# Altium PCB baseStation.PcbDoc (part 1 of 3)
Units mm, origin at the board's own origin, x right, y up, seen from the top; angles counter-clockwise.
Board outline 130 x 90 mm, 4 copper layers (Top Layer, Ground Layer, Power Layer, Bottom Layer), stack 1.574 mm thick; 252 components, 154 nets, 772 pads, 1223 vias.
Unrouted connection lines stored in the file: 134.
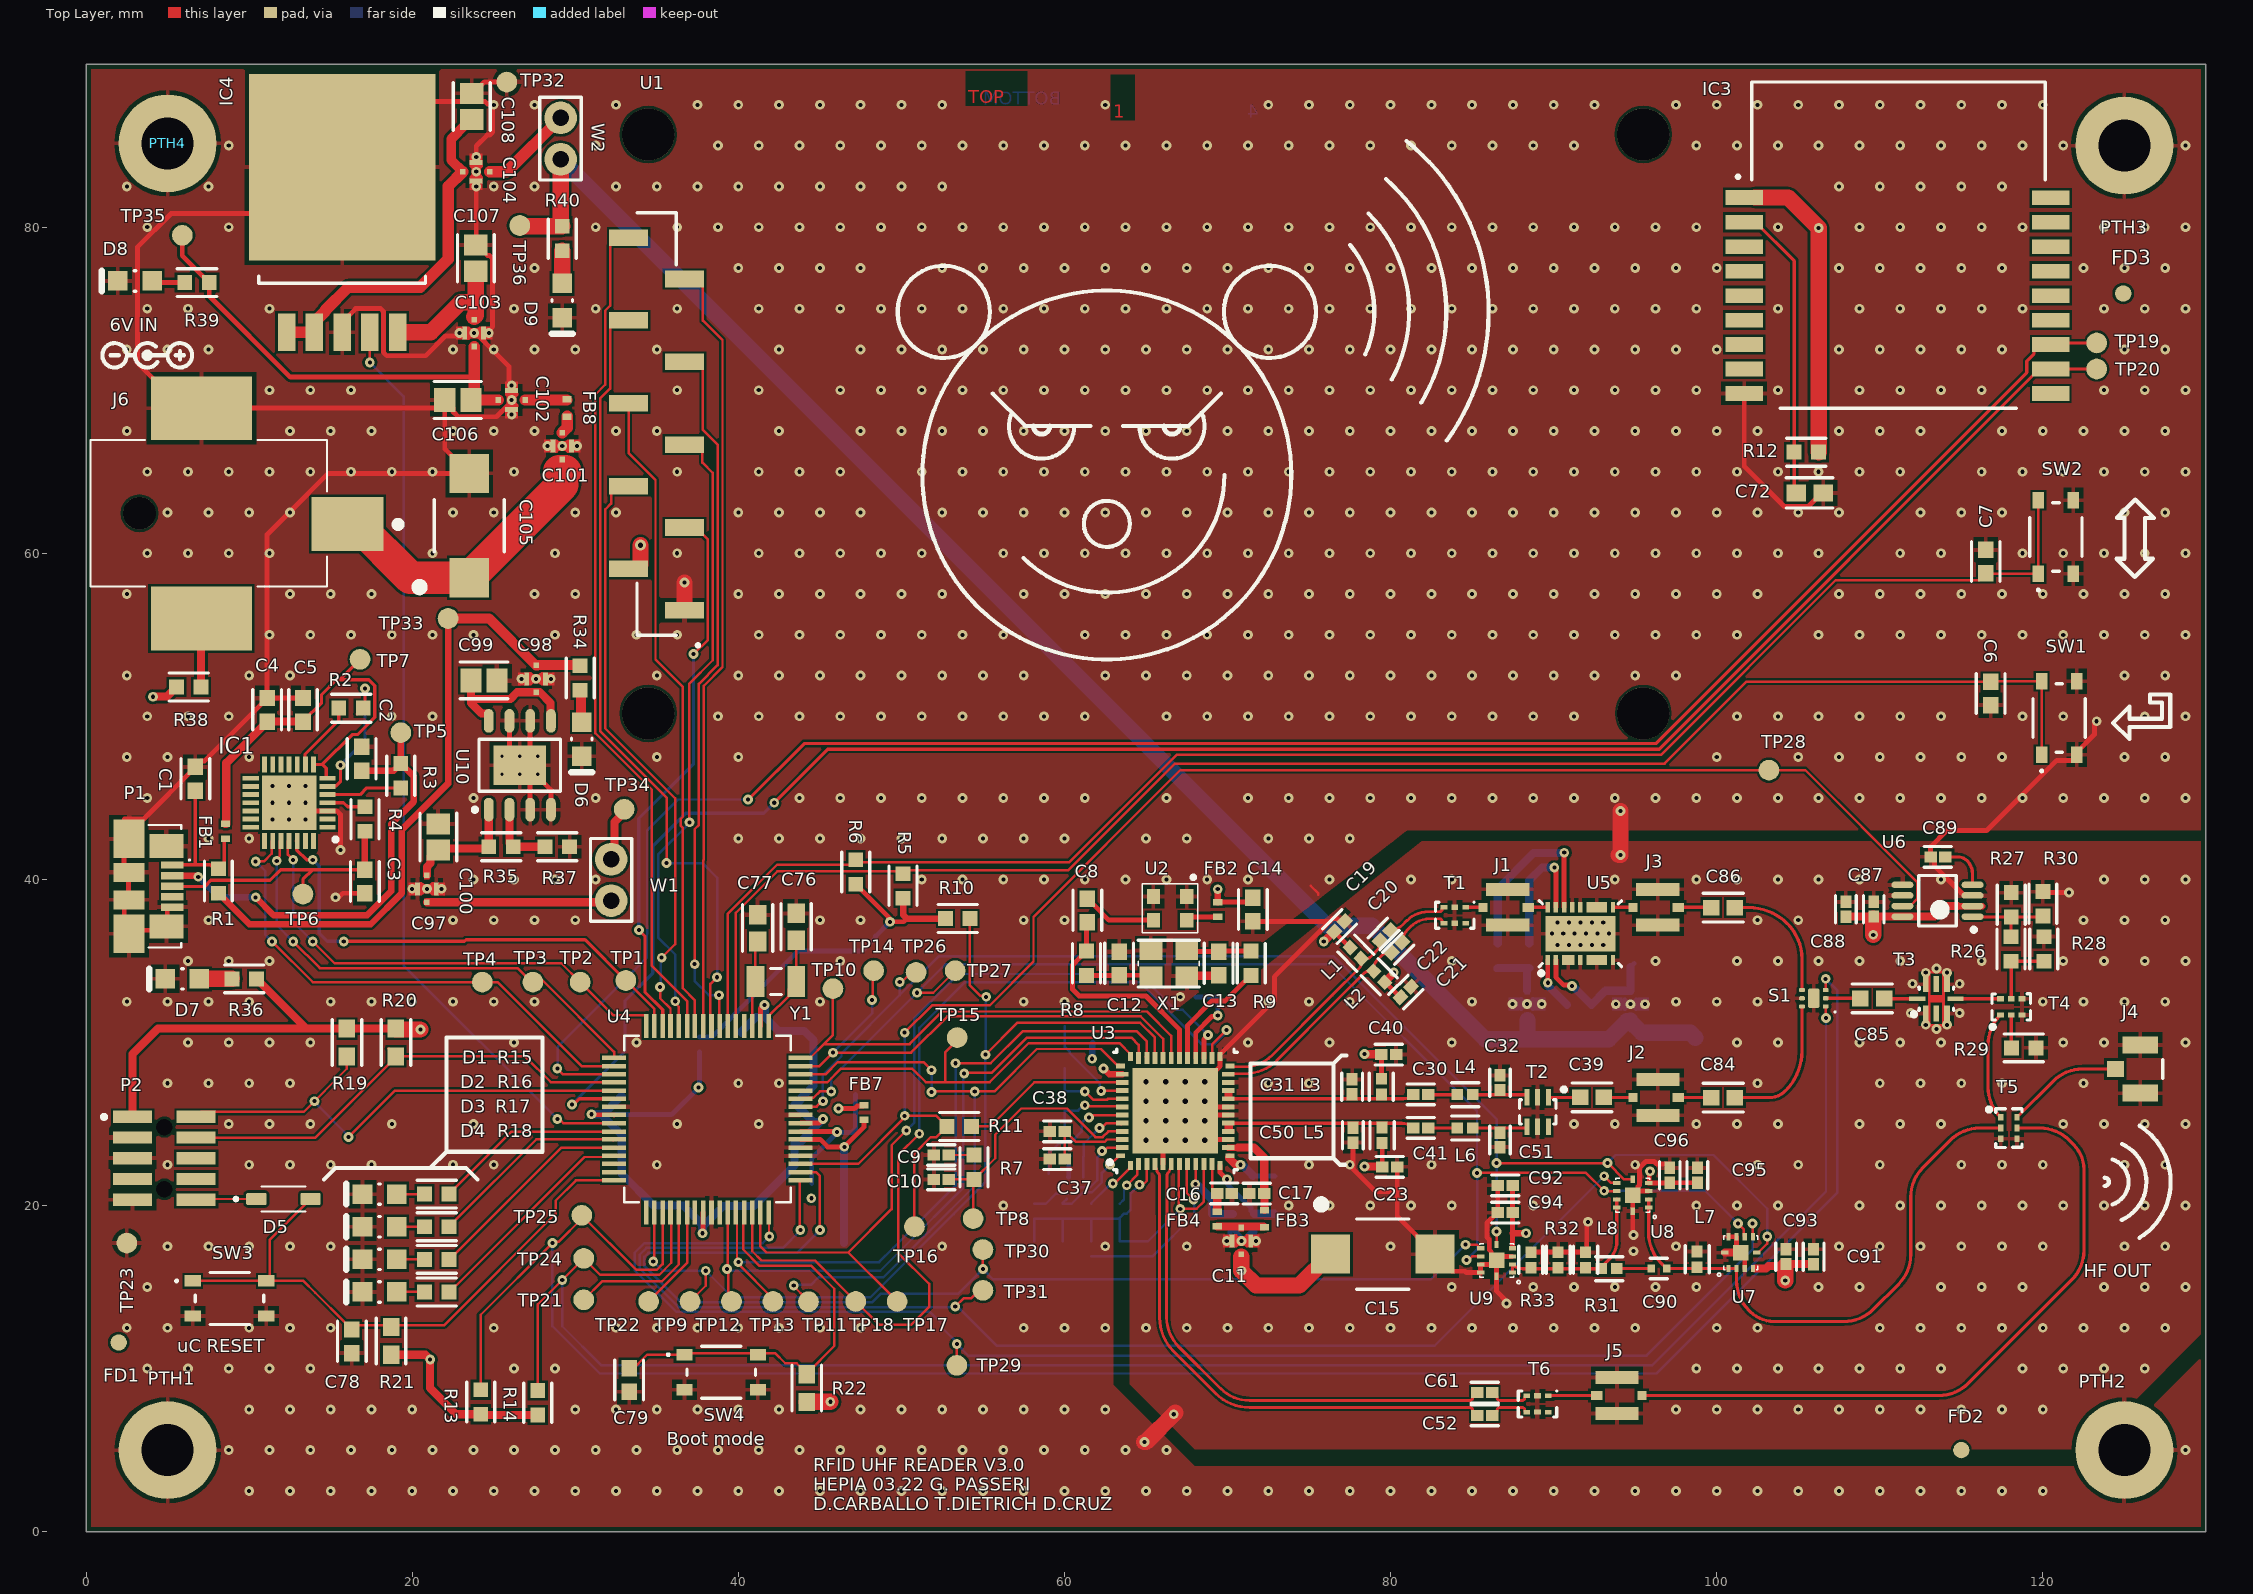
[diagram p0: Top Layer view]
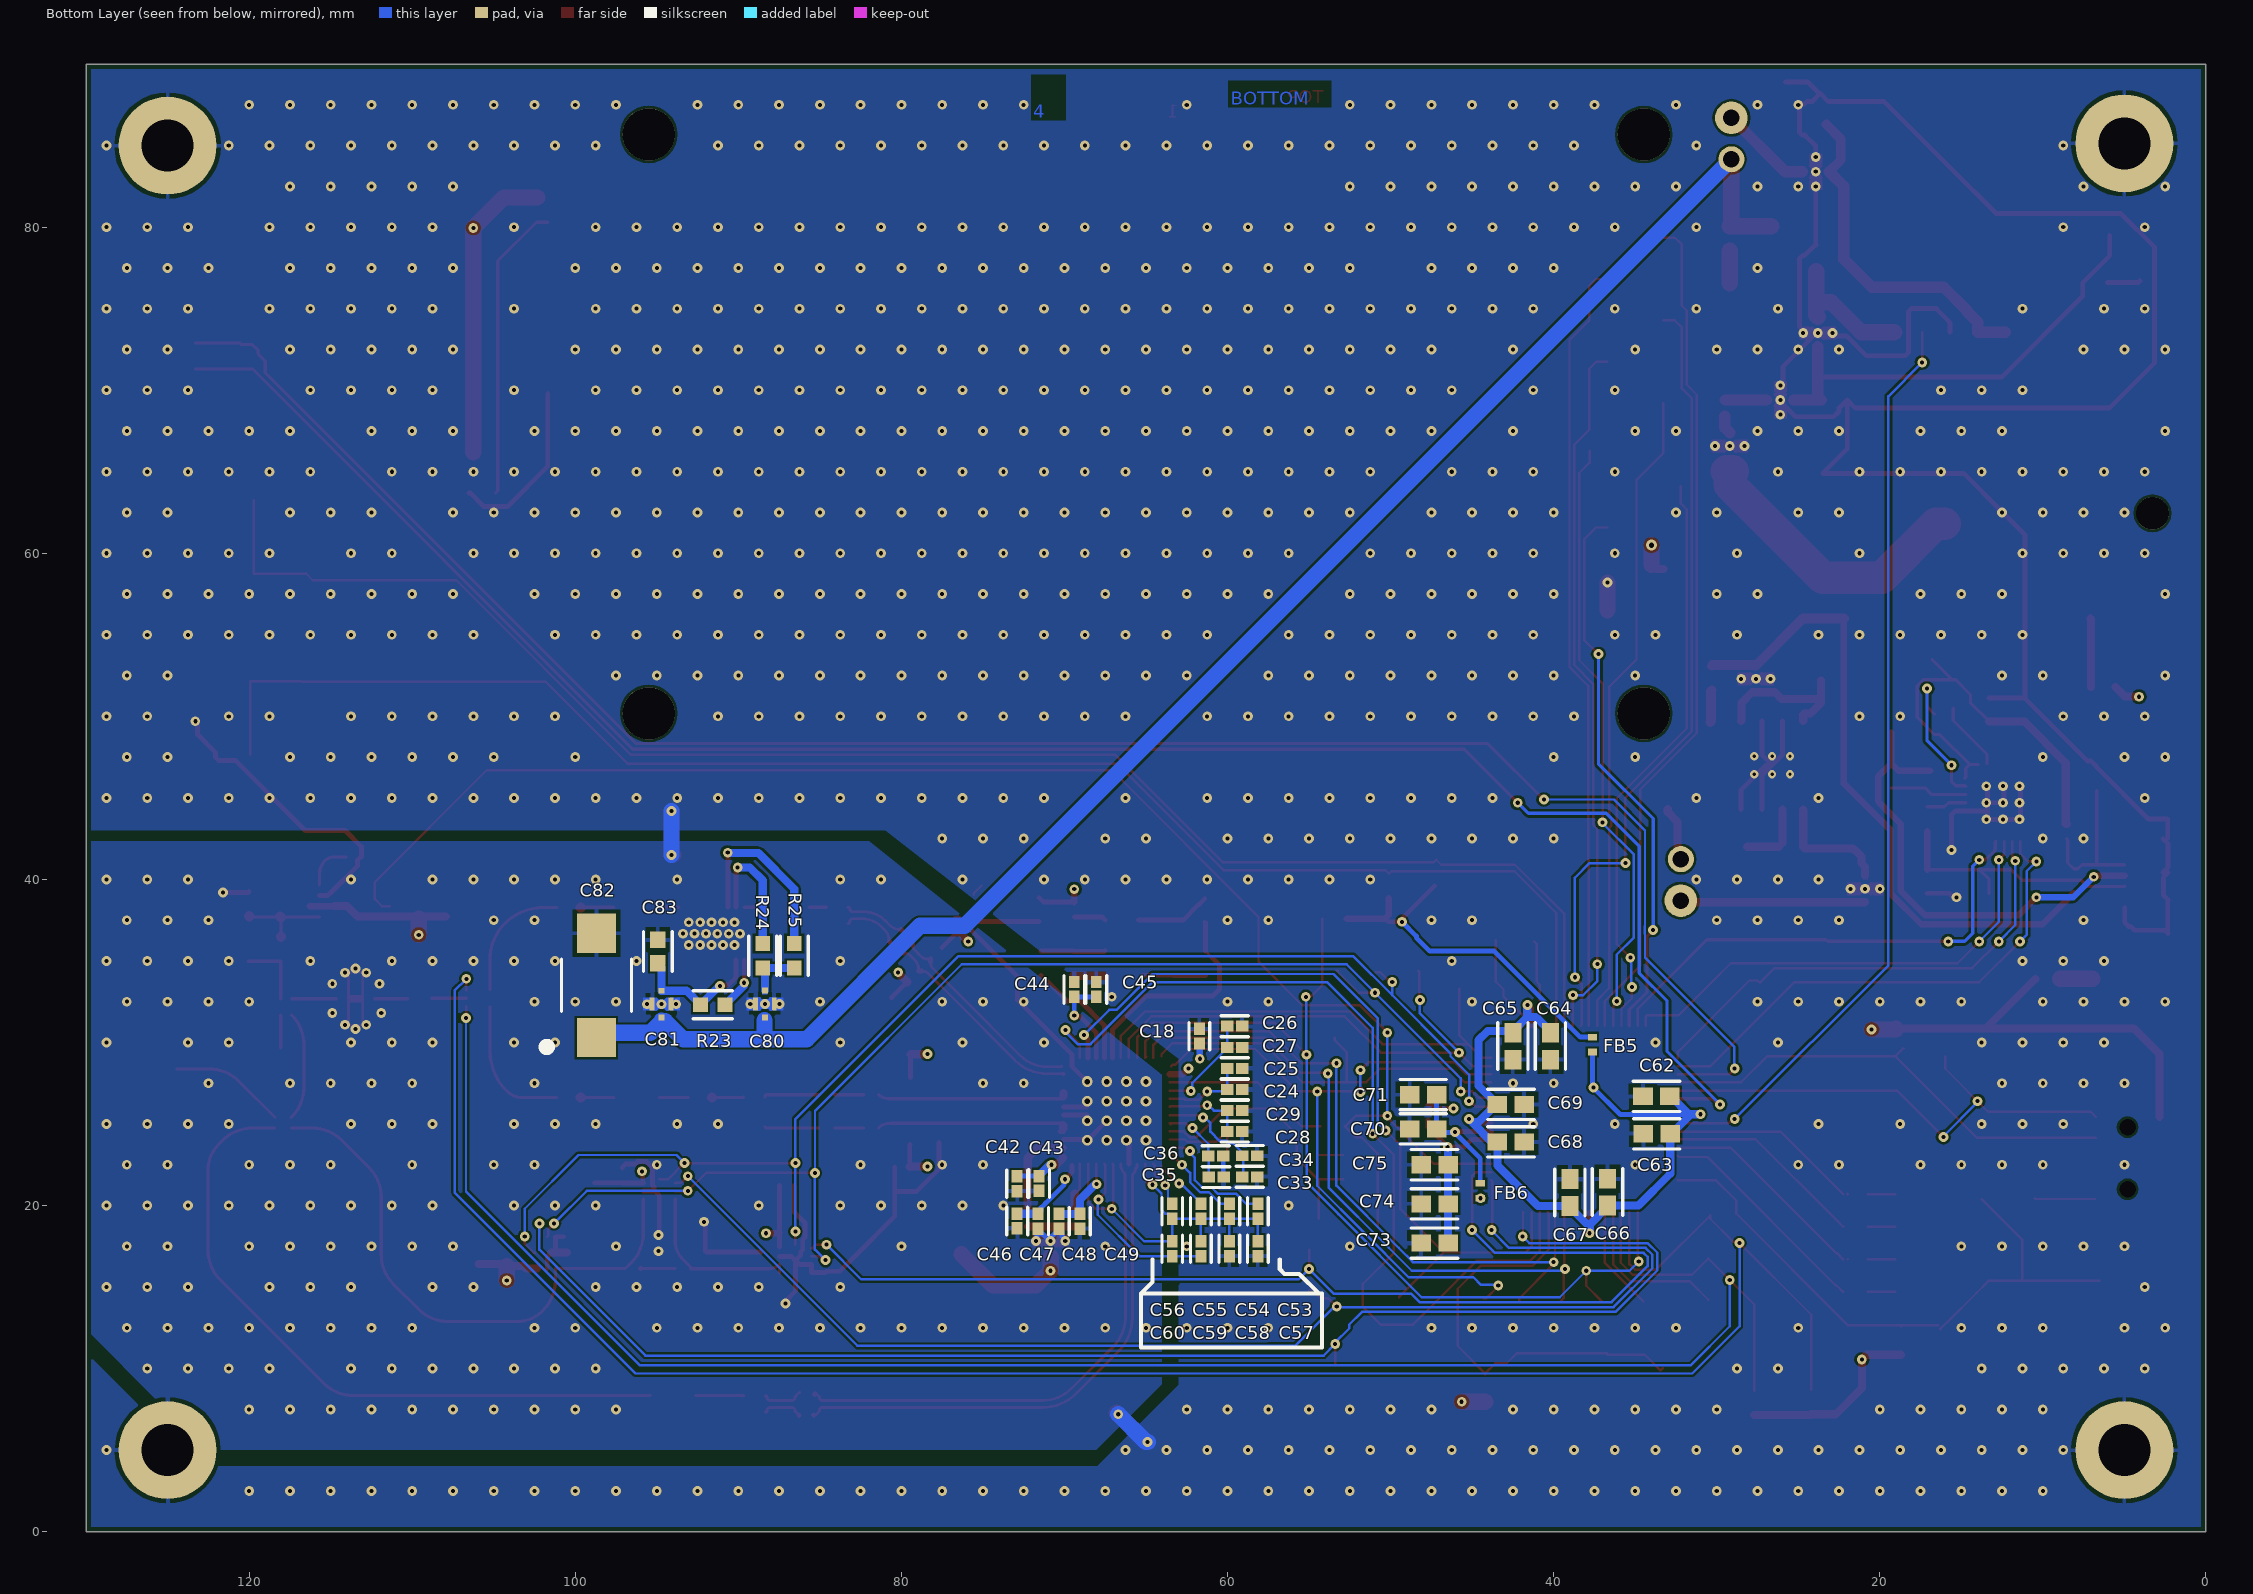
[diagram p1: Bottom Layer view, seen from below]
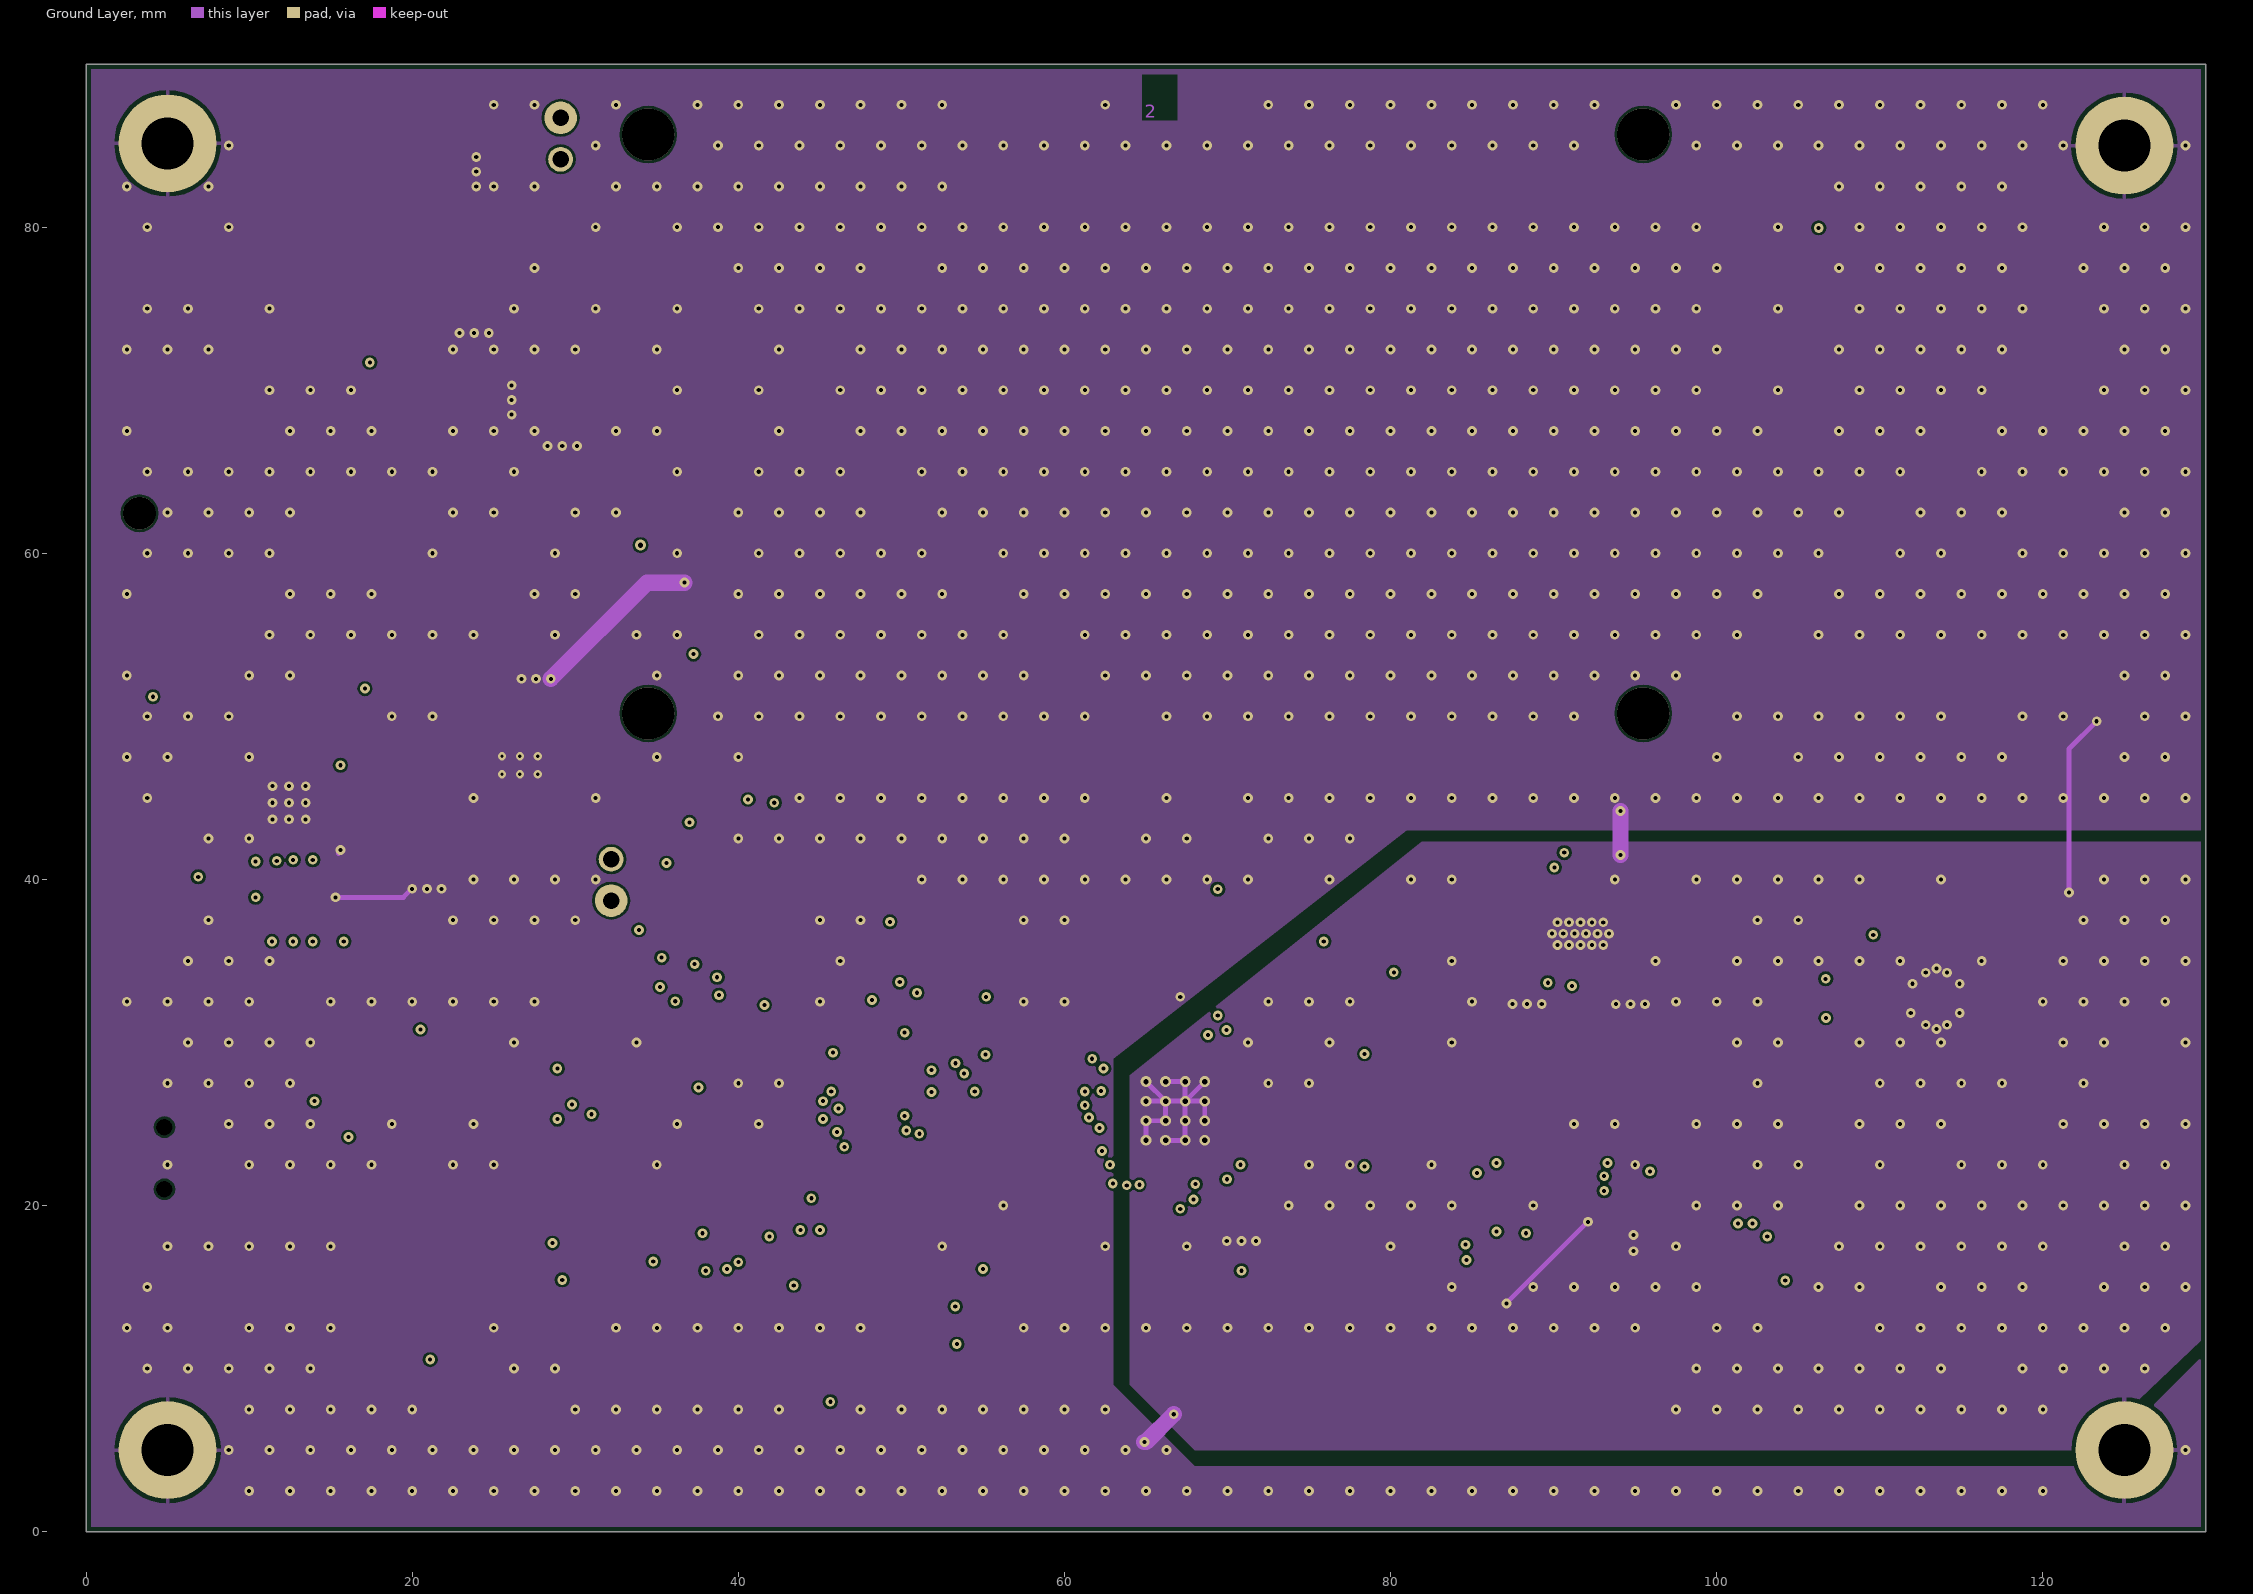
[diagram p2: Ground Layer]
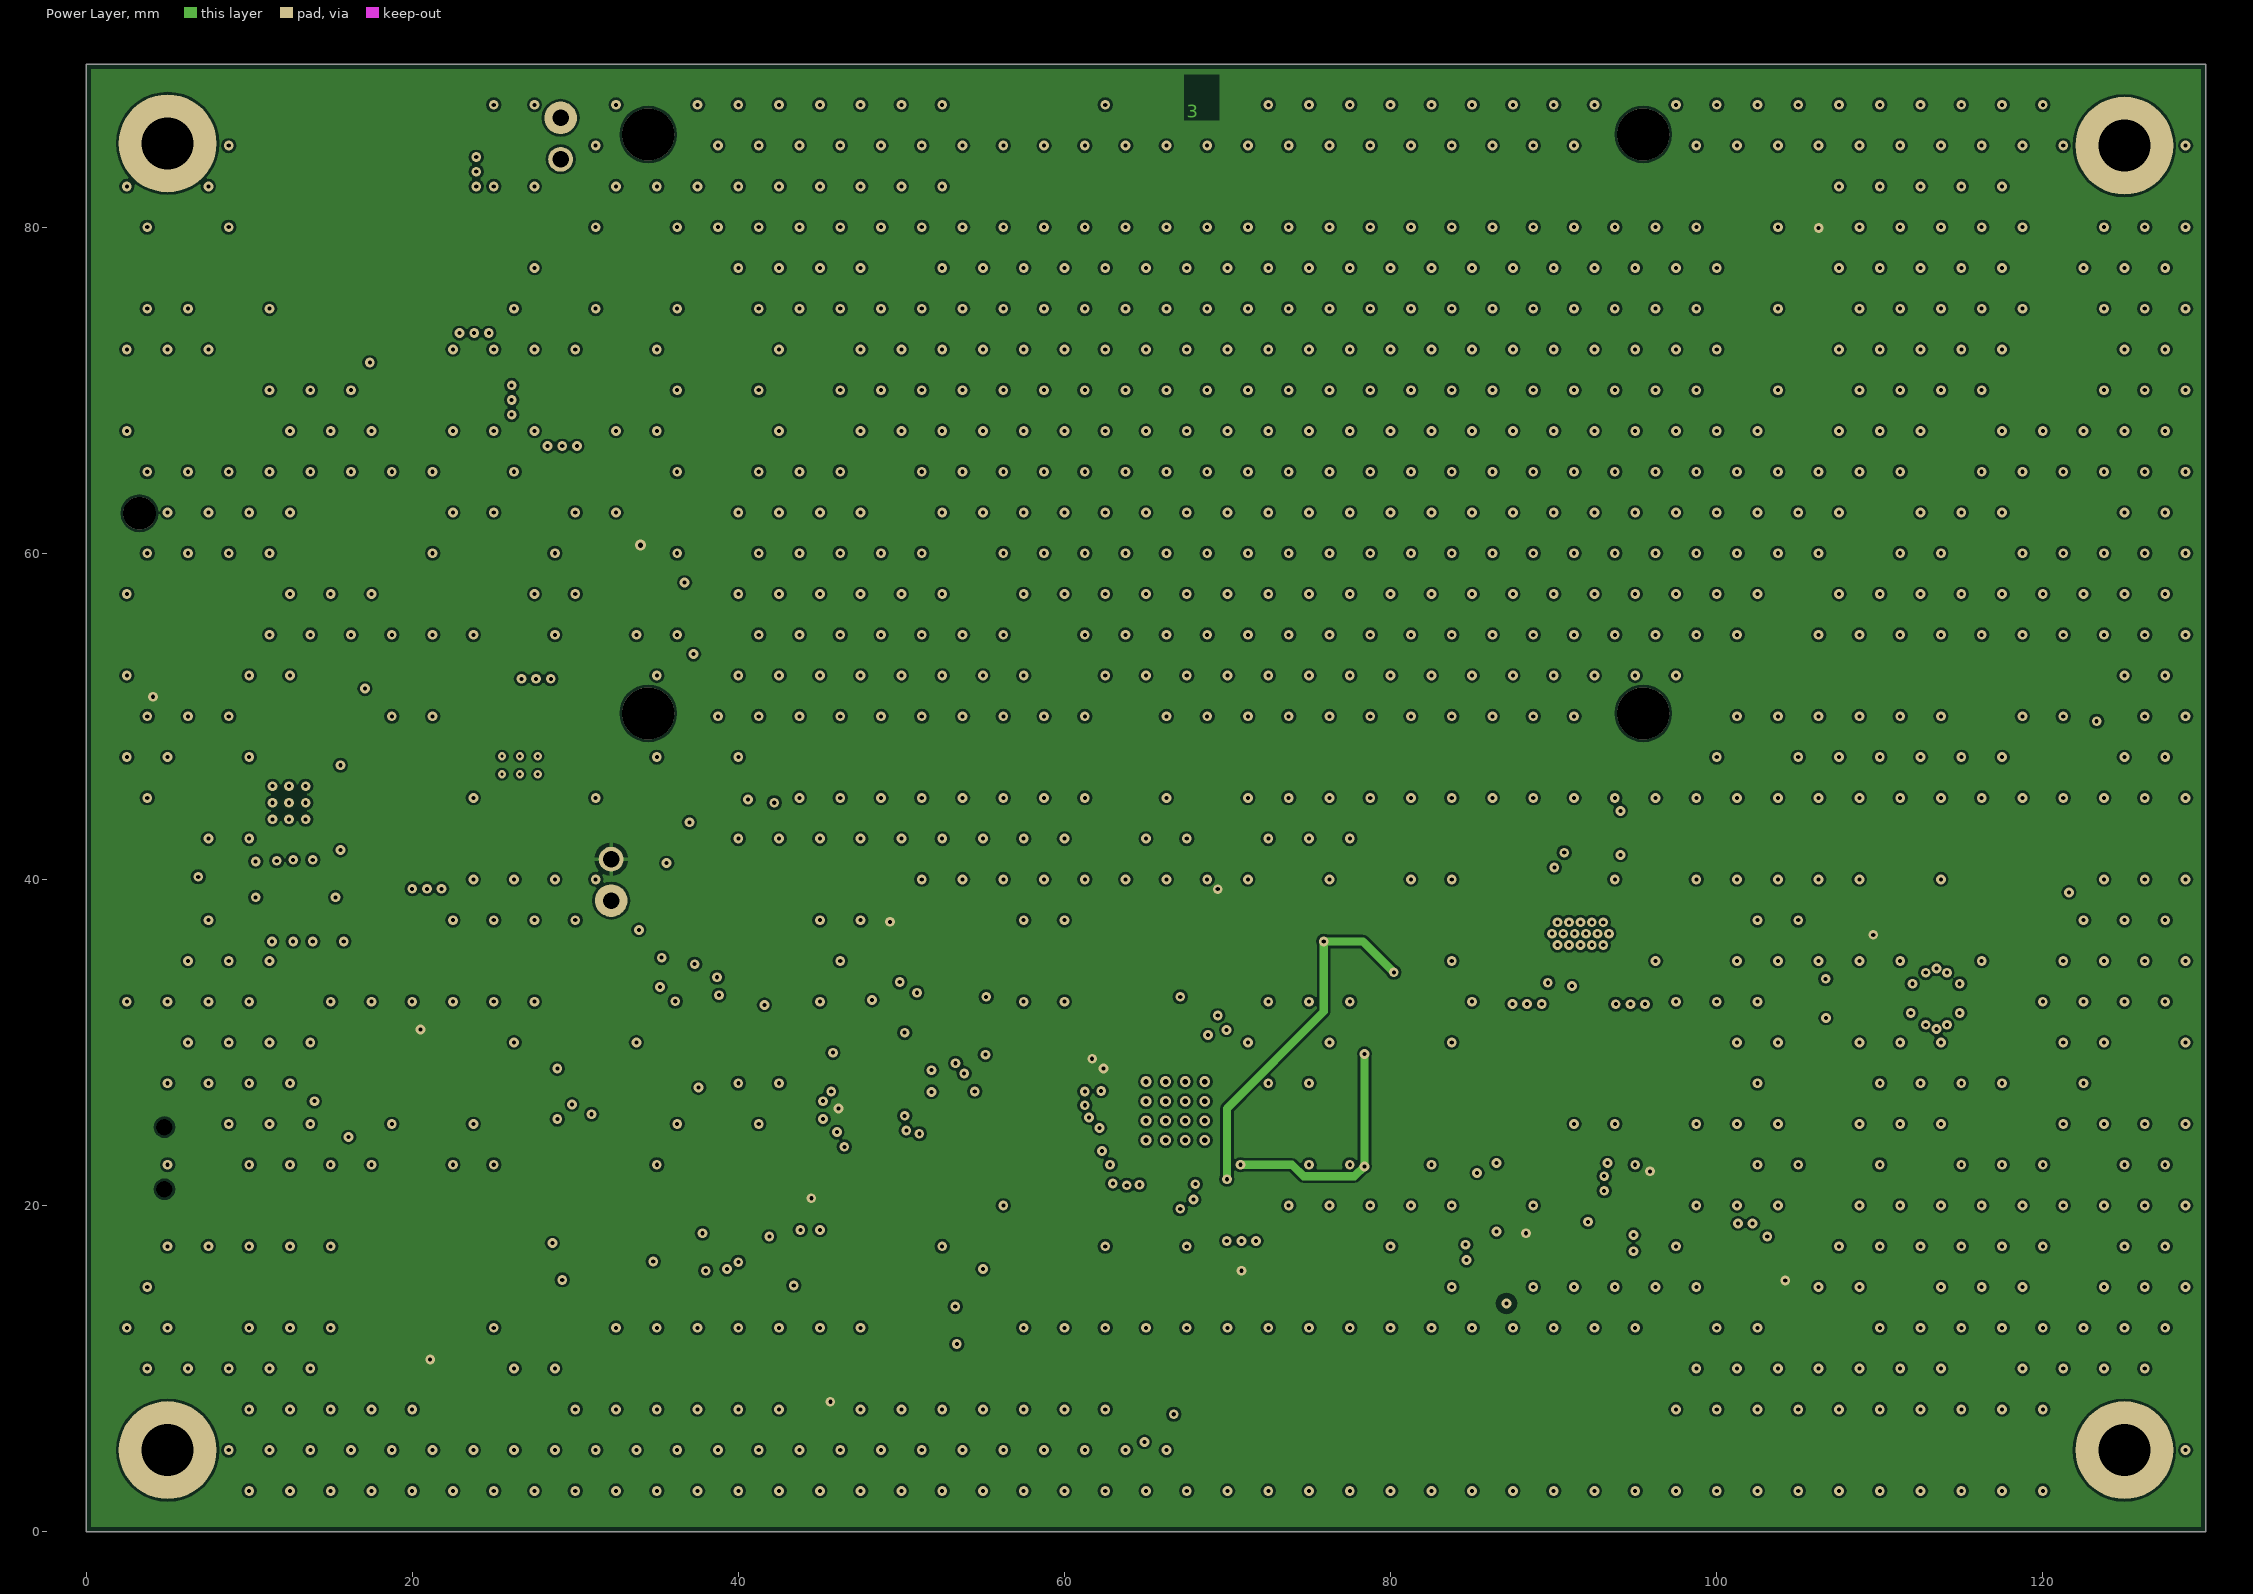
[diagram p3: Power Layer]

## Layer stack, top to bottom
Top Solder: solder mask 0.0102, Solder Resist, Dk 3.5
Top Layer: signal copper 0.035
Dielectric 1: prepreg 0.1168, PP-016, Dk 4.4
Ground Layer: signal copper 0.035
Dielectric 2: core 1.2, FR-4, Dk 4.3
Power Layer: signal copper 0.035
Dielectric 3: prepreg 0.1168, PP-016, Dk 4.4
Bottom Layer: signal copper 0.035
Bottom Solder: solder mask 0.0102, Solder Resist, Dk 3.5

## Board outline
0,0 130,0 130,90 0,90

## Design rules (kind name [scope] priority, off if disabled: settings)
BoardOutlineClearance [All] p1: gap=0.3 ignorepadtopadclearanceinfootprint=FALSE
Clearance [All] p1: gap=0.15 ignorepadtopadclearanceinfootprint=FALSE
DiffPairsRouting [All] p1: maxlimit=0.254 minlimit=0.254 mostfreqgap=0.254 toplayer_minwidth=0.381 toplayer_maxwidth=0.381 toplayer_prefwidth=0.381 midlayer1_minwidth=0.381 midlayer1_maxwidth=0.381 midlayer1_prefwidth=0.381 midlayer2_minwidth=0.381 midlayer2_maxwidth=0.381 midlayer2_prefwidth=0.381 bottomlayer_minwidth=0.381 bottomlayer_maxwidth=0.381 bottomlayer_prefwidth=0.381 maxuncoupledlength=12.7
HoleSize [All] p1: absolutevalues=TRUE maxlimit=3.3 minlimit=0.025 maxpercent=80.000 minpercent=20.000
MaxMinImpedance "Schematic Impedance Constraint_35" [InNet('IN_P')] p1: minimum=100,0 maximum=100,0
MaxMinImpedance "Schematic Impedance Constraint_34" [InNet('TX_P')] p2: minimum=100,0 maximum=100,0
MaxMinImpedance "Schematic Impedance Constraint_33" [InNet('IN_N')] p3: minimum=100,0 maximum=100,0
MaxMinImpedance "Schematic Impedance Constraint_32" [InNet('TX_N')] p4: minimum=100,0 maximum=100,0
MaxMinImpedance "Schematic Impedance Constraint_31" [InNet('RFO_P')] p5: minimum=100,0 maximum=100,0
MaxMinImpedance "Schematic Impedance Constraint_30" [InNet('RFO_N')] p6: minimum=100,0 maximum=100,0
MaxMinImpedance "Schematic Impedance Constraint_29" [InNet('RX_N')] p7: minimum=100,0 maximum=100,0
MaxMinImpedance "Schematic Impedance Constraint_28" [InNet('RX_P')] p8: minimum=100,0 maximum=100,0
MaxMinImpedance "Schematic Impedance Constraint_27" [InNet('NetT3_4')] p9: minimum=50,00 maximum=50,00
MaxMinImpedance "Schematic Impedance Constraint_26" [InNet('NetC84_2')] p10: minimum=50,00 maximum=50,00
MaxMinImpedance "Schematic Impedance Constraint_25" [InNet('NetR29_1')] p11: minimum=50,00 maximum=50,00
MaxMinImpedance "Schematic Impedance Constraint_24" [InNet('TX')] p12: minimum=50,00 maximum=50,00
MaxMinImpedance "Schematic Impedance Constraint_23" [InNet('NetC30_2')] p13: minimum=50,00 maximum=50,00
MaxMinImpedance "Schematic Impedance Constraint_22" [InNet('NetC86_1')] p14: minimum=50,00 maximum=50,00
MaxMinImpedance "Schematic Impedance Constraint_21" [InNet('NetR26_2')] p15: minimum=50,00 maximum=50,00
MaxMinImpedance "Schematic Impedance Constraint_20" [InNet('NetC39_2')] p16: minimum=50,00 maximum=50,00
MaxMinImpedance "Schematic Impedance Constraint_19" [InNet('NetL8_1')] p17: minimum=50,00 maximum=50,00
MaxMinImpedance "Schematic Impedance Constraint_18" [InNet('CCC')] p18: minimum=50,00 maximum=50,00
MaxMinImpedance "Schematic Impedance Constraint_17" [InNet('NetC39_1')] p19: minimum=50,00 maximum=50,00
MaxMinImpedance "Schematic Impedance Constraint_16" [InNet('PA_OUT')] p20: minimum=50,00 maximum=50,00
MaxMinImpedance "Schematic Impedance Constraint_15" [InNet('NetJ5_OUT')] p21: minimum=50,00 maximum=50,00
MaxMinImpedance "Schematic Impedance Constraint_14" [InNet('NetC86_2')] p22: minimum=50,00 maximum=50,00
MaxMinImpedance "Schematic Impedance Constraint_13" [InNet('NetJ5_IN')] p23: minimum=50,00 maximum=50,00
MaxMinImpedance "Schematic Impedance Constraint_12" [InNet('NetC85_1')] p24: minimum=50,00 maximum=50,00
MaxMinImpedance "Schematic Impedance Constraint_11" [InNet('NetC84_1')] p25: minimum=50,00 maximum=50,00
MaxMinImpedance "Schematic Impedance Constraint_10" [InNet('NetC51_2')] p26: minimum=50,00 maximum=50,00
MaxMinImpedance "Schematic Impedance Constraint_9" [InNet('PAOUT_N')] p27: minimum=50,00 maximum=50,00
MaxMinImpedance "Schematic Impedance Constraint_8" [InNet('NetC41_2')] p28: minimum=50,00 maximum=50,00
MaxMinImpedance "Schematic Impedance Constraint_7" [InNet('TX_RX')] p29: minimum=50,00 maximum=50,00
MaxMinImpedance "Schematic Impedance Constraint_6" [InNet('NetC32_2')] p30: minimum=50,00 maximum=50,00
MaxMinImpedance "Schematic Impedance Constraint_5" [InNet('LP_FILTER_IN')] p31: minimum=50,00 maximum=50,00
MaxMinImpedance "Schematic Impedance Constraint_4" [InNet('NetC90_1')] p32: minimum=50,00 maximum=50,00
MaxMinImpedance "Schematic Impedance Constraint_3" [InNet('NetJ1_OUT')] p33: minimum=50,00 maximum=50,00
MaxMinImpedance "Schematic Impedance Constraint_2" [InNet('NetR26_1')] p34: minimum=50,00 maximum=50,00
MaxMinImpedance "Schematic Impedance Constraint_1" [InNet('PAOUT_P')] p35: minimum=50,00 maximum=50,00
MaxMinImpedance "Schematic Impedance Constraint" [InNet('NetJ1_IN')] p36: minimum=50,00 maximum=50,00
MinimumSolderMaskSliver [All] p1: minsoldermaskwidth=0.075
PlaneConnect [All] p1: pad.planeconnectstyle=Relief pad.reliefexpansion=0.508 pad.reliefentries=4 pad.reliefconductorwidth=0.254 pad.reliefairgap=0.254 via.planeconnectstyle=Direct via.reliefexpansion=0.508 via.reliefentries=4 via.reliefconductorwidth=0.254 via.reliefairgap=0.254
PolygonConnect [All] p1: thpad.connectstyle=Relief thpad.reliefconductorwidth=0.254 thpad.reliefentries=4 thpad.polygonreliefangle="90 Angle" thpad.airgapwidth=0.254 smdpad.connectstyle=Relief smdpad.reliefconductorwidth=0.254 smdpad.reliefentries=4 smdpad.polygonreliefangle="90 Angle" smdpad.airgapwidth=0.254 via.connectstyle=Direct via.reliefconductorwidth=0.254 via.reliefentries=4 via.polygonreliefangle="90 Angle" via.airgapwidth=0.254
RoutingVias [All] p1: holewidth=0.711 width=1 viastyle="Through Hole" minholewidth=0.5 minwidth=0.7 maxholewidth=0.711 maxwidth=1
SilkToSolderMaskClearance [IsPad] p1: minsilkscreentomaskgap=0 clearancetoexposedcopper=TRUE
SolderMaskExpansion [All] p1: expansion=0.03 istentingtop=FALSE
Width [All] p1: maxlimit=2 minlimit=0.15 preferedwidth=0.15
25 further rules are at their usual default settings.

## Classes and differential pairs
component class Sheet6: C87 C88 C89 C90 C91 C92 C93 C94 C95 C96 J4 J5 L7 L8 R26 R27 R28 R29 R30 R31 R32 R33 T4 T5 T6 TP26 TP27 TP28 TP29 TP30 TP31 U6 U7 U8 U9
component class Sheet5: C80 C81 C82 C83 C84 C85 C86 J3 R23 R24 R25 S1 T3 TP24 TP25 U5
component class Sheet4: C8 C9 C10 C11 C12 C13 C14 C15 C16 C17 C18 C19 C20 C21 C22 C23 C24 C25 C26 C27 C28 C29 C30 C31 C32 C33 C34 C35 C36 C37 C38 C39 C40 C41 C42 C43 C44 C45 C46 C47 C48 C49 C50 C51 C52 C53 C54 C55 C56 C57 C58 C59 C60 C61 FB2 FB3 FB4 J1 J2 L1 L2 L3 L4 L5 L6 R7 R8 R9 R10 R11 T1 T2 TP8 TP9 TP10 TP11 TP12 TP13 TP14 TP15 TP16 TP17 TP18 U2 U3 X1
component class Sheet3: C62 C63 C64 C65 C66 C67 C68 C69 C70 C71 C72 C73 C74 C75 C76 C77 C78 C79 D1 D2 D3 D4 D5 FB5 FB6 FB7 IC3 P2 R12 R13 R14 R15 R16 R17 R18 R19 R20 R21 R22 SW3 SW4 TP19 TP20 TP21 TP22 TP23 U4 Y1
component class Sheet2: C1 C2 C3 C4 C5 C6 C7 FB1 IC1 P1 R1 R2 R3 R4 R5 R6 SW1 SW2 TP1 TP2 TP3 TP4 TP5 TP6 TP7 U1
component class Sheet1: C97 C98 C99 C100 C101 C102 C103 C104 C105 C106 C107 C108 D6 D7 D8 D9 FB8 IC4 J6 R34 R35 R36 R37 R38 R39 R40 TP32 TP33 TP34 TP35 TP36 U10 W1 W2
component class baseStation: FD1 FD2 FD3 PTH1 PTH2 PTH3 PTH4
differential pair TX: +TX_P -TX_N
differential pair RFO: +RFO_P -RFO_N
differential pair RX: +RX_P -RX_N
differential pair IN: +IN_P -IN_N

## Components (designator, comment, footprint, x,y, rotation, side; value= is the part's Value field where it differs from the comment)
C1 "Cap" FP-C0603C-CF-IPC_B 6.7,46.174 r270 top value=10nF
C2 "Cap" FP-C0603C-CF-IPC_B 16.9,47.4 r270 top value=47pF
C3 "Cap" FP-C0603C-CF-IPC_B 17.1,39.874 r90 top value=47pF
C4 "Cap" FP-C0603C-CF-IPC_B 11.1,50.4 r270 top value=4u7F
C5 "Cap" FP-C0603C-CF-IPC_B 13.3,50.4 r270 top value=100nF
C6 "Cap" FP-C0603C-CF-IPC_B 116.8,51.4 r90 top value=100nF
C7 "Cap" FP-C0603C-CF-IPC_B 116.5,59.5 r270 top value=100nF
C8 "" FP-C0603C-CF-IPC_B 61.4,38.1 r270 top value=220nF
C9 "" FP-PRF15-0_05-IPC_A 52.45,23.1 r180 top value=3n9F
C10 "" FP-PRF15-0_05-IPC_A 52.45,21.6 r180 top value=150pF
C11 "0.47uF" NFM18PS 70.85,17.83 r90 top
C12 "" FP-C0603C-CF-IPC_B 63.35,34.85 r90 top value=11pF
C13 "" FP-C0603C-CF-IPC_B 69.45,34.85 r270 top value=11pF
C14 "" FP-C0603C-CF-IPC_B 71.55,38.15 r270 top value=100nF
C15 "" 2917(7343) 79.52,17.02 r0 top
C16 "Cap" FP-PRF15-0_05-IPC_A 69.814,20.74 r0 top value=2u2F
C17 "Cap" FP-PRF15-0_05-IPC_A 71.8,20.73 r180 top value=2u2F
C18 "Low ESL" FP-PRF15-0_05-IPC_A 61.73,30.394 r90 bottom value=100nF
C19 "Cap" FP-PRF15-0_05-IPC_A 76.87,37.11 r45 top value=120pF
C20 "Cap" FP-PRF15-0_05-IPC_A 79.662,36.572 r45 top value=82pF
C21 "Cap" FP-PRF15-0_05-IPC_A 80.93,33.09 r45 top value=120pF
C22 "Cap" FP-PRF15-0_05-IPC_A 80.39,35.83 r45 top value=82pF
C23 "Cap" FP-PRF15-0_05-IPC_A 79.95,22.37 r0 top value=120pF
C24 "Cap" FP-PRF15-0_05-IPC_A 59.556,27.117 r180 bottom value=2u2F
C25 "Cap" FP-PRF15-0_05-IPC_A 59.556,28.411 r180 bottom value=120pF
C26 "Cap" FP-PRF15-0_05-IPC_A 59.556,31 r180 bottom value=2u2F
C27 "Cap" FP-PRF15-0_05-IPC_A 59.556,29.706 r180 bottom value=120pF
C28 "Cap" FP-PRF15-0_05-IPC_A 59.556,24.528 r180 bottom value=2u2F
C29 "Cap" FP-PRF15-0_05-IPC_A 59.556,25.822 r180 bottom value=120pF
C30 "Cap" FP-PRF15-0_05-IPC_A 81.85,26.82 r0 top value=15pF
C31 "Cap" FP-PRF15-0_05-IPC_A 77.64,27.29 r90 top value=1p2F
C32 "Cap" FP-PRF15-0_05-IPC_A 86.71,27.54 r270 top value=5p6F
C33 "Cap" FP-PRF15-0_05-IPC_A 58.636,21.759 r180 bottom value=2u2F
C34 "Cap" FP-PRF15-0_05-IPC_A 58.636,23.053 r180 bottom value=30pF
C35 "Cap" FP-PRF15-0_05-IPC_A 60.7,21.74 r180 bottom value=2u2F
C36 "Cap" FP-PRF15-0_05-IPC_A 60.73,23.03 r180 bottom value=30pF
C37 "Cap" FP-PRF15-0_05-IPC_A 59.55,22.85 r180 top value=2u2F
C38 "Cap" FP-PRF15-0_05-IPC_A 59.55,24.55 r180 top value=120pF
C39 "Cap" FP-C0603C-CF-IPC_B 92.35,26.63 r0 top value=82pF
C40 "Cap" FP-PRF15-0_05-IPC_A 79.89,29.26 r0 top value=120pF
C41 "Cap" FP-PRF15-0_05-IPC_A 81.85,24.76 r0 top value=15pF
C42 "Cap" FP-PRF15-0_05-IPC_A 72.9,21.34 r270 bottom value=2u2F
C43 "Low ESL" FP-PRF15-0_05-IPC_A 71.55,21.35 r270 bottom value=100nF
C44 "Cap" FP-PRF15-0_05-IPC_A 69.4,33.25 r90 bottom value=2u2F
C45 "Cap" FP-PRF15-0_05-IPC_A 68.05,33.25 r90 bottom value=30pF
C46 "Cap" FP-PRF15-0_05-IPC_A 72.9,19.05 r270 bottom value=2u2F
C47 "Low ESL" FP-PRF15-0_05-IPC_A 71.62,19.03 r270 bottom value=100nF
C48 "Cap" FP-PRF15-0_05-IPC_A 70.34,19.03 r270 bottom value=2u2F
C49 "Low ESL" FP-PRF15-0_05-IPC_A 69.05,19.03 r270 bottom value=100nF
C50 "Cap" FP-PRF15-0_05-IPC_A 77.69,24.31 r270 top value=1p2F
C51 "Cap" FP-PRF15-0_05-IPC_A 86.71,24.02 r90 top value=5p6F
C52 "Cap" FP-PRF15-0_05-IPC_A 85.78,7.13 r0 top value=82pF
C53 "Cap" FP-PRF15-0_05-IPC_A 58.14,19.644 r270 bottom value=10nF
C54 "Cap" FP-PRF15-0_05-IPC_A 59.89,19.65 r270 bottom value=10nF
C55 "Cap" FP-PRF15-0_05-IPC_A 61.64,19.65 r270 bottom value=10nF
C56 "Cap" FP-PRF15-0_05-IPC_A 63.39,19.65 r270 bottom value=10nF
C57 "Cap" FP-PRF15-0_05-IPC_A 58.14,17.35 r270 bottom value=2u2F
C58 "Low ESL" FP-PRF15-0_05-IPC_A 59.89,17.35 r270 bottom value=100nF
C59 "Cap" FP-PRF15-0_05-IPC_A 61.64,17.35 r270 bottom value=2u2F
C60 "Low ESL" FP-PRF15-0_05-IPC_A 63.39,17.35 r270 bottom value=100nF
C61 "Cap" FP-PRF15-0_05-IPC_A 85.78,8.53 r0 top value=82pF
C62 "Cap" FP-C0603C-CF-IPC_A 33.7,26.7 r180 bottom value=100nF
C63 "Cap" FP-C0603C-CF-IPC_A 33.674,24.4 r180 bottom value=10nF
C64 "Cap" FP-C0603C-CF-IPC_A 40.2,29.774 r90 bottom value=100nF
C65 "Cap" FP-C0603C-CF-IPC_A 42.5,29.774 r90 bottom value=10nF
C66 "Cap" FP-C0603C-CF-IPC_A 36.7,20.826 r270 bottom value=100nF
C67 "Cap" FP-C0603C-CF-IPC_A 39,20.8 r270 bottom value=10nF
C68 "Cap" FP-C0603C-CF-IPC_A 42.626,23.9 r0 bottom value=100nF
C69 "Cap" FP-C0603C-CF-IPC_A 42.626,26.2 r0 bottom value=10nF
C70 "Cap" FP-C0603C-CF-IPC_A 48,24.7 r180 bottom value=100nF
C71 "Cap" FP-C0603C-CF-IPC_A 48,26.8 r180 bottom value=10uF
C72 "Cap" FP-C0603C-CF-IPC_A 105.7,63.7 r180 top value=1uF
C73 "Cap" FP-C0603C-CF-IPC_A 47.3,17.7 r180 bottom value=100nF
C74 "Cap" FP-C0603C-CF-IPC_A 47.3,20.1 r180 bottom value=100nF
C75 "Cap" FP-C0603C-CF-IPC_A 47.3,22.5 r180 bottom value=10uF
C76 "Cap" FP-C0603C-CF-IPC_A 43.544,37.1 r270 top value=22pF
C77 "Cap" FP-C0603C-CF-IPC_A 41.185,37.015 r90 top value=22pF
C78 "Cap" FP-C0603C-CF-IPC_B 16.3,11.674 r90 top value=100nF
C79 "Cap" FP-C0603C-CF-IPC_B 33.3,9.3 r90 top value=100nF
C80 "0.47uF" NFM18PS 88.37,32.36 r90 bottom
C81 "0.47uF" NFM18PS 94.71,32.35 r90 bottom
C82 "10uF" 2917(7343) 98.7,33.5 r90 bottom
C83 "Cap" FP-C0603C-CF-IPC_B 94.94,35.58 r270 bottom value=2u2F
C84 "Cap" FP-C0603C-CF-IPC_B 100.39,26.62 r0 top value=82pF
C85 "Cap" FP-C0603C-CF-IPC_B 109.54,32.7 r0 top value=82pF
C86 "Cap" FP-C0603C-CF-IPC_B 100.39,38.27 r0 top value=82pF
C87 "Cap" FP-PRF15-0_05-IPC_A 109.63,38.18 r270 top value=120pF
C88 "Cap" FP-PRF15-0_05-IPC_A 107.92,38.17 r270 top value=2u2F
C89 "Cap" FP-PRF15-0_05-IPC_A 113.57,41.38 r0 top value=2n2F
C90 "Cap" FP-PRF15-0_05-MFG 96.45,16.14 r0 top value=1p6F
C91 "Cap" FP-PRF15-0_05-IPC_A 105.94,16.86 r90 top value=2u2F
C92 "Cap" FP-PRF15-0_05-IPC_A 87.03,21.241 r180 top value=2u2F
C93 "Cap" FP-PRF15-0_05-IPC_A 104.25,16.87 r90 top value=120pF
C94 "Cap" FP-PRF15-0_05-IPC_A 87.03,19.561 r180 top value=120pF
C95 "Cap" FP-PRF15-0_05-IPC_A 98.81,21.85 r90 top value=2u2F
C96 "Cap" FP-PRF15-0_05-IPC_A 97.12,21.85 r90 top value=120pF
C97 "" NFM18PS 20.9,39.422 r270 top
C98 "" NFM18PS 27.6,52.3 r270 top
C99 "Cap" FP-C0805C-DN-IPC_B 24.399,52.2 r180 top value=2u2F
C100 "Cap" FP-C0805C-DN-IPC_B 21.6,42.6 r270 top value=2u2F
C101 "" NFM18PS 29.2,66.575 r90 top
C102 "" NFM18PS 26.1,69.4 r180 top
C103 "" NFM18PS 23.8,73.5 r90 top
C104 "" NFM18PS 23.925,83.4 r0 top
C105 "" 2917(7343) 23.5,61.7 r90 top
C106 "Cap" FP-C0805C-DN-IPC_B 22.799,69.4 r0 top value=2u2F
C107 "Cap" FP-C0805C-DN-IPC_B 23.9,78.101 r270 top value=2u2F
C108 "Cap" FP-C0805C-DN-IPC_B 23.653,87.4 r270 top value=22uf
D1 "" LTST-C170KRKT_V 18,20.7 r0 top
D2 "" LTST-C170KRKT_V 18,18.7 r0 top
D3 "" LTST-C170KRKT_V 18,16.7 r0 top
D4 "" LTST-C170KRKT_V 18,14.7 r0 top
D5 "" SOD3715X135N 12.1,20.4 r0 top
D6 "" LTST-C170KRKT_V 30.4,48.6 r90 top
D7 "" LTST-C170KRKT_V 5.9,33.9 r0 top
D8 "" LTST-C170KRKT_V 3,76.7 r0 top
D9 "" LTST-C170KRKT_V 29.2,75.5 r90 top
FB1 "1k" L0402-RF 8.539,42.946 r90 top
FB2 "1k" L0402-RF 69.4,38.15 r270 top
FB3 "" FB0402-RF 72.26,19.19 r90 top
FB4 "1k" L0402-RF 69.37,19.17 r90 top
FB5 "1k" L0402-RF 37.63,29.87 r270 bottom
FB6 "1k" L0402-RF 44.5,20.9 r90 bottom
FB7 "1k" L0402-RF 47.7,25.7 r90 top
FB8 "" FB0402-RF 29.5,68.9 r90 top
FD1 "FID1X2R" FID1X2R 2,11.6 r0 top
FD2 "FID1X2R" FID1X2R 115,5 r90 top
FD3 "FID1X2R" FID1X2R 124.93,75.933 r90 top
IC1 "CP2101-GMR" QFN50P500X500X100-29N-D 12.45,44.7 r180 top
IC3 "ESP32-C3-WROOM-02-N4" ESP32C3WROOM02N4 112.1,75.6 r0 top
IC4 "LT1529CQ-5#PBF" LT1529CQ5PBF 15.7,81 r0 top
J1 "" MS-156HF 87.18,38.29 r270 top
J2 "" MS-156HF 96.39,26.63 r270 top
J3 "" MS-156HF 96.385,38.29 r270 top
J4 "" FP-U_FL-R-SMT-1_10-MFG 125.97,28.37 r90 top
J5 "" MS-156HF 93.88,8.35 r90 top
J6 "" CUI_PJ-036BH-SMT-TR 16.025,61.8 r0 top
L1 "Inductor" FP-LQG15HH_02-IPC_A 77.86,35.48 r315 top value=30nH
L2 "Inductor" FP-LQG15HH_02-IPC_A 79.3,34.03 r135 top value=30nH
L3 "Inductor" FP-LQG15HH_02-IPC_A 79.43,27.29 r270 top value=30nH
L4 "Inductor" FP-LQG15HH_02-IPC_A 84.569,26.8 r0 top value=3n6F
L5 "Inductor" FP-LQG15HH_02-IPC_A 79.48,24.31 r90 top value=30nH
L6 "Inductor" FP-LQG15HH_02-IPC_A 84.569,24.76 r0 top value=3n6F
L7 "Inductor" FP-LQG15HH_02-IPC_A 98.8,16.7 r90 top value=6n8H
L8 "Inductor" FP-LQG15HH_02-IPC_A 91.96,16.661 r90 top value=6n2H
P1 "47346-0001" MOLEX_47346-0001 2.636,39.583 r270 top
P2 "" HDR2X5_SMT 4.8,22.9 r270 top
PTH1 "mounting hole" M3-HOLE 5,5 r0 top
PTH2 "mounting hole" M3-HOLE 125,5 r0 top
PTH3 "mounting hole" M3-HOLE 125,85 r0 top
PTH4 "mounting hole" M3-HOLE 5,85.135 r0 top
R1 "" FP-RC1608-IPC_B 8.115,39.9 r270 top value=NC
R2 "" FP-RC1608-IPC_B 16.251,50.5 r0 top value=4.7k
R3 "" FP-RC1608-IPC_B 19.3,46.36 r270 top value=27R
R4 "" FP-RC1608-IPC_B 17.1,43.7 r90 top value=27R
R5 "" FP-RC1608-IPC_B 50.1,39.6 r270 top value=10k
R6 "" FP-RC1608-IPC_B 47.198,40.451 r270 top value=10k
R7 "" FP-RC1608-IPC_B 54.45,22.35 r90 top value=15k
R8 "" FP-RC1608-IPC_B 61.35,34.85 r90 top value=NC
R9 "" FP-RC1608-IPC_B 71.45,34.85 r90 top value=NC
R10 "" FP-RC1608-IPC_B 53.449,37.6 r0 top value=10k
R11 "" FP-RC1608-IPC_B 53.55,24.85 r0 top value=NC
R12 "" FP-RC1608-IPC_B 105.5,66.2 r0 top value=10k
R13 "" FP-RC1608-IPC_B 24.2,7.949 r90 top value=10k
R14 "" FP-RC1608-IPC_B 27.7,7.9 r90 top value=10k
R15 "" FP-RC1608-IPC_B 21.5,20.7 r0 top value=680R
R16 "" FP-RC1608-IPC_B 21.5,18.7 r0 top value=680R
R17 "" FP-RC1608-IPC_B 21.5,16.7 r0 top value=680R
R18 "" FP-RC1608-IPC_B 21.5,14.7 r0 top value=680R
R19 "" FP-RC1608-IPC_A 16,30 r90 top value=10K
R20 "" FP-RC1608-IPC_A 19,30 r90 top value=10K
R21 "" FP-RC1608-IPC_A 18.7,11.7 r270 top value=10K
R22 "" FP-RC1608-IPC_A 44.2,8.8 r270 top value=10K
R23 "Res2" FP-RC1608-IPC_B 91.57,32.31 r0 bottom value=100R
R24 "Res2" FP-RC1608-IPC_B 88.5,35.319 r270 bottom value=0R
R25 "Res2" FP-RC1608-IPC_B 86.57,35.32 r270 bottom value=0R
R26 "Res2" FP-RC1608-IPC_B 118.05,35.73 r90 top value=249R
R27 "Res2" FP-RC1608-IPC_B 118.06,38.44 r90 top value=62R
R28 "Res2" FP-RC1608-IPC_B 120.06,35.73 r90 top value=62R
R29 "Res2" FP-RC1608-IPC_B 118.83,29.67 r0 top value=51.1R
R30 "Res2" FP-RC1608-IPC_B 120,38.5 r90 top value=52.3R
R31 "Res2" FP-RC1005-IPC_A 93.4,16.13 r180 top value=0R
R32 "Res2" FP-RC1005-IPC_A 90.28,16.661 r90 top value=110R
R33 "Res2" FP-RC1005-IPC_A 88.6,16.661 r90 top value=100R
R34 "" FP-RC1608-IPC_B 30.3,52.351 r90 top value=1k5
R35 "" FP-RC1608-IPC_B 25.449,42 r180 top value=31k6
R36 "" FP-RC1608-IPC_B 9.7,33.9 r0 top value=680R
R37 "" FP-RC1608-IPC_B 28.9,42 r180 top value=10k
R38 "" FP-RC1608-IPC_B 6.3,51.8 r180 top value=NC
R39 "" FP-RC1608-IPC_B 6.8,76.6 r0 top value=1k5
R40 "" FP-RC1608-IPC_B 29.2,79.3 r90 top value=1k5
S1 "" SKY13431-374LF 105.955,32.71 r180 top
SW1 "FSM4JSMA" RKB2SJK250SMTRLFS 121,49.9 r90 top
SW2 "FSM4JSMA" RKB2SJK250SMTRLFS 120.8,61 r90 top
SW3 "FSM4JSMA" RKB2SJK250SMTRLFS 8.8,14.3 r0 top
SW4 "FSM4JSMA" RKB2SJK250SMTRLFS 38.95,9.775 r0 top
T1 "" BD0810J50100AHF 83.94,37.8 r270 top
T2 "" JTI-0900BL15C050 89.02,25.74 r270 top
T3 "" JTI-0900LP15B0063 113.47,32.68 r0 top
T4 "" DC0710J5010AHF 118.06,32.18 r90 top
T5 "" DC0710J5010AHF 117.92,24.75 r0 top
T6 "" BD0810J50100AHF 89.01,7.83 r270 top
TP1 "Test point" PIN_DE_TEST 33.1,33.8 r180 top
TP2 "Test point" PIN_DE_TEST 30.3,33.7 r180 top
TP3 "Test point" PIN_DE_TEST 27.4,33.7 r180 top
TP4 "Test point" PIN_DE_TEST 24.3,33.7 r0 top
TP5 "Test point" PIN_DE_TEST 19.3,49 r90 top
TP6 "Test point" PIN_DE_TEST 13.3,39.1 r90 top
TP7 "Test point" PIN_DE_TEST 16.8,53.5 r90 top
TP8 "Test point" PIN_DE_TEST 54.4,19.2 r0 top
TP9 "Test point" PIN_DE_TEST 37.04,14.12 r90 top
TP10 "Test point" PIN_DE_TEST 45.8,33.3 r90 top
TP11 "Test point" PIN_DE_TEST 44.3,14.1 r90 top
TP12 "Test point" PIN_DE_TEST 39.58,14.12 r90 top
TP13 "Test point" PIN_DE_TEST 42.12,14.12 r90 top
TP14 "Test point" PIN_DE_TEST 48.3,34.4 r90 top
TP15 "Test point" PIN_DE_TEST 53.42,30.3 r90 top
TP16 "Test point" PIN_DE_TEST 50.8,18.7 r270 top
TP17 "Test point" PIN_DE_TEST 49.74,14.12 r90 top
TP18 "Test point" PIN_DE_TEST 47.2,14.12 r90 top
TP19 "Test point" PIN_DE_TEST 123.3,72.9 r180 top
TP20 "Test point" PIN_DE_TEST 123.3,71.3 r180 top
TP21 "Test point" PIN_DE_TEST 30.52,14.22 r0 top
TP22 "Test point" PIN_DE_TEST 34.5,14.12 r180 top
TP23 "Test point" PIN_DE_TEST 2.5,17.7 r180 top
TP24 "Test point" PIN_DE_TEST 30.52,16.76 r90 top
TP25 "Test point" PIN_DE_TEST 30.4,19.4 r90 top
TP26 "Test point" PIN_DE_TEST 50.9,34.3 r90 top
TP27 "Test point" PIN_DE_TEST 53.3,34.4 r90 top
TP28 "Test point" PIN_DE_TEST 103.2,46.7 r180 top
TP29 "Test point" PIN_DE_TEST 53.4,10.2 r0 top
TP30 "Test point" PIN_DE_TEST 55,17.3 r0 top
TP31 "Test point" PIN_DE_TEST 55,14.8 r0 top
TP32 "Test point" PIN_DE_TEST 25.8,88.9 r0 top
TP33 "Test point" PIN_DE_TEST 22.2,56 r180 top
TP34 "Test point" PIN_DE_TEST 33,44.3 r180 top
TP35 "Test point" PIN_DE_TEST 5.9,79.5 r90 top
TP36 "Test point" PIN_DE_TEST 26.6,80.1 r90 top
U1 "" ADAFRUIT_1480 31.936,67.931 r0 top
U2 "" TY_TYPE_2.5X2.0MM 66.475,38.225 r180 top
U3 "ST25RU3993" ST25RU3993_QFN48_0.5MM_PITCH 66.8,25.8 r90 top
U4 "LPC54114J256BD64QL" QFP50P1200X1200X160-64N 38.1,25.3 r90 top
U5 "" TQP9107 91.64,36.67 r180 top
U6 "" MAX4003 113.54,38.69 r180 top
U7 "" PE62304 101.47,17.11 r90 top
U8 "" PE62304 94.85,20.63 r180 top
U9 "" PE62304 86.5,16.631 r180 top
U10 "755-BD00IC0MEFJ-ME2" HTSOP-J8 26.6,47 r90 top
W1 "current measurement" PLUG_THMD_STRIP2 32.2,38.7 r90 top
W2 "current measurement" PLUG_THMD_STRIP2 29.1,86.7 r270 top
X1 "" NX3225SA 66.4,34.85 r0 top
Y1 "" FP-ECX-34Q-MFG 42.3,33.735 r180 top

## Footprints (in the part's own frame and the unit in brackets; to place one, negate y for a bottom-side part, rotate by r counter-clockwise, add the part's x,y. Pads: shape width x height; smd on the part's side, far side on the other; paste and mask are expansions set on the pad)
2917(7343) [mm] "Chip Capacitor, 2-Leads, Body 7,30x4,30mm, IPC Medium Density"
  rect 2.4x2.4 smd: 1(-3.2,0) 2(3.2,0)
  silkscreen extent -4.02,-2.15 1.6,3.3, body extent -3.86,-2.25 3.85,2.25, height 1.91
ADAFRUIT_1480 [mm] "SPI LCD MODULE 2.2\" 320x240p"
  rect 2.41x1.02 smd: 1(4.764,-11.431) 2(1.334,-8.891) 3(4.764,-6.351) 4(1.334,-3.811) 5(4.764,-1.271) 6(1.334,1.269) 7(4.764,3.809) 8(1.334,6.349) 9(4.764,8.889) 10(1.334,11.429)
  round 3.2 hole 3.2 unplated: ""(2.54,-17.75) ""(2.54,17.75) ""(63.56,-17.75) ""(63.56,17.755)
  silkscreen extent 1.84,-13.68 5.69,12.95, body extent 0.4,-20.47 66.94,20.53, height 14
BD0810J50100AHF [mm] "RF Balun 800MHz ~ 1GHz 50 / 100 Ohm 0805"
  rect 0.27x0.41 smd mask+0.04: 1(-0.495,0.66) 3(-0.495,-0.66) 4(0.495,-0.66) 6(0.495,0.66)
  rect 0.33x0.41 smd mask+0.04: 2(-0.495,0) 5(0.495,0)
  silkscreen extent -0.8,-1.19 0.8,1.18, body extent -0.65,-1.03 0.65,1.03, height 0.86
CUI_PJ-036BH-SMT-TR [mm]
  rect 4.4x3.3 smd: 1(0,0)
  rect 6.2x3.9 smd: 2(-8.95,7.1) 3(-8.95,-5.8)
  round 2 hole 2 unplated: ""(-12.75,0.65)
  silkscreen extent -15.75,-3.85 3.3,5.15, body extent -15.87,-6.96 1.23,8.24, height 11.1
DC0710J5010AHF [mm] "Directional Coupler"
  rect 0.33x0.41 smd mask+0.04: 1(-0.495,0.66) 2(-0.495,0) 3(-0.495,-0.66) 4(0.495,-0.66) 5(0.495,0) 6(0.495,0.66)
  silkscreen extent -1.35,-1.19 0.8,1.26, body extent -0.65,-1.03 0.65,1.03, height 0.86
ESP32C3WROOM02N4 [mil]
  rect 90x35.43 smd: 1(-410,245) 2(-410,185.04) 3(-410,125.98) 4(-410,66.93) 5(-410,7.87) 6(-410,-51.18) 7(-410,-110.24) 8(-410,-169.29) 9(-410,-228.35) 10(330,-228.35) 11(330,-169.29) 12(330,-110.24) 13(330,-51.18) 14(330,7.87) 15(330,66.93) 16(330,125.98) 17(330,185.04) 18(330,244.09)
  silkscreen extent -429,-264 317,524, body extent -394,-269 314,519, height 126
FB0402-RF [mil] "Ferrite Bead"
  rect 15.75x22 smd paste+0 mask+0: 1(-21,0) 2(21,0)
  body extent -22,-11 22,11, height 12
FID1X2R [mm] "Fiducial - Round 1x2mm"
  round 1 smd paste-0.5 mask+0.5: 0(0,0)
FP-C0603C-CF-IPC_A [mil]
  rect 47.5x41.66 smd paste+0 mask+0: 1(-32.51,0) 2(32.51,0)
  silkscreen extent -56,-37 56,37, body extent -31,-16 31,16, height 34
FP-C0603C-CF-IPC_B [mm]
  rect 1.007x0.958 smd paste+0 mask+0: 1(-0.726,0) 2(0.726,0)
  silkscreen extent -1.23,-0.88 1.23,0.88, body extent -1.48,-0.73 1.48,0.73, height 0.25
FP-C0805C-DN-IPC_B [mm]
  rect 1.305x1.456 smd paste+0 mask+0: 1(-0.801,0) 2(0.801,0)
  silkscreen extent -1.45,-1.13 1.45,1.13, body extent -1.7,-0.98 1.7,0.98, height 0.25
FP-ECX-34Q-MFG [mm]
  rect 1.1x1.9 smd paste+0 mask+0: 1(-1.25,0) 2(1.25,0)
  silkscreen extent -0.33,-0.8 0.33,0.8, body extent -1.9,-1.05 1.9,1.05, height 0.25
FP-LQG15HH_02-IPC_A [mm]
  rect 0.715x0.672 smd paste+0 mask+0: 1(-0.479,0) 2(0.479,0)
  silkscreen extent -0.84,-0.74 0.84,0.74, body extent -1.04,-0.54 1.04,0.54, height 0.25
FP-PRF15-0_05-IPC_A [mm]
  rect 0.761x0.672 smd paste+0 mask+0: 1(-0.456,0) 2(0.456,0)
  silkscreen extent -0.84,-0.64 0.83,0.64, body extent -1.04,-0.54 1.04,0.54, height 0.25
FP-PRF15-0_05-MFG [mm]
  rect 0.45x0.5 smd paste+0 mask+0: 1(-0.475,0) 2(0.475,0)
  silkscreen extent -0.53,-0.63 0.53,0.63, body extent -0.8,-0.38 0.8,0.38, height 0.25
FP-RC1005-IPC_A [mm]
  rect 0.715x0.672 smd paste+0 mask+0: 1(-0.479,0) 2(0.479,0)
  silkscreen extent -0.84,-0.74 0.84,0.74, body extent -1.04,-0.54 1.04,0.54, height 0.25
FP-RC1608-IPC_A [mm]
  rect 1.11x1.012 smd paste+0 mask+0: 1(-0.851,0) 2(0.851,0)
  silkscreen extent -1.41,-0.91 1.41,0.91, body extent -1.91,-1.01 1.91,1.01, height 0.25
FP-RC1608-IPC_B [mm]
  rect 0.91x0.912 smd paste+0 mask+0: 1(-0.751,0) 2(0.751,0)
  silkscreen extent -1.21,-0.86 1.21,0.86, body extent -1.46,-0.71 1.46,0.71, height 0.25
FP-U_FL-R-SMT-1_10-MFG [mm]
  rect 1x1.05 smd paste-1000 mask+0: 1(0,1.525)
  rect 1.05x2.2 smd paste-1000 mask+0: 2(-1.475,0) 3(1.475,0)
  silkscreen extent -0.58,-1.38 0.58,-1.38, body extent -2.1,-1.48 2.1,2.15, height 0.25
HDR2X5_SMT [mm] "Header, 10-Leads, Body 3.43x6.35mm, Pitch 1.27mm"
  rect 0.76x2.4 smd: 1(-2.54,-1.95) 2(-2.54,1.95) 3(-1.27,-1.95) 4(-1.27,1.95) 5(0,-1.95) 6(0,1.95) 7(1.27,-1.95) 8(1.27,1.95) 9(2.54,-1.95) 10(2.54,1.95)
  round 0 hole 1 unplated: MH1(-1.905,0) MH2(1.905,0)
  silkscreen extent -2.66,-3.82 -2.42,-3.57, body extent -3.18,-1.72 3.18,1.72, height 4.55
HTSOP-J8 [mm] "HTSOP, 8-Leads, Body 4.90x3.90mm, Pitch 1.27mm, Thermal Pad 3.20x2.40mm, IPC Medium Density"
  oval 1.45x0.6 smd: 1(-2.725,1.905) 2(-2.725,0.635) 3(-2.725,-0.635) 4(-2.725,-1.905) 5(2.725,-1.905) 6(2.725,-0.635) 7(2.725,0.635) 8(2.725,1.905)
  rect 2.4x3.2 smd: 9(0,0)
  silkscreen extent -2.85,-2.5 1.6,2.88, body extent -2,-2.5 2,2.5, height 1
JTI-0900BL15C050 [mm] "900 MHz Balun 1:1"
  rect 1x0.3 smd mask+0.07: 1(-0.9,0.66) 2(-0.9,0) 3(-0.9,-0.65) 4(0.9,-0.65) 5(0.9,0) 6(0.9,0.66)
  silkscreen extent -1.5,-1.12 0.74,1.73, body extent -0.64,-1.02 0.65,1.02, height 0.86
JTI-0900LP15B0063 [mm] "900 MHz Low Pass Filter"
  rect 0.35x1 smd mask+0.05: 1(-0.65,-0.9) 2(0,-0.9) 3(0.65,-0.9) 5(0.65,0.9) 6(0,0.9) 7(-0.65,0.9)
  rect 1x0.27 smd mask+0.05: 4(1.175,0) 8(-1.175,0)
  Top Layer region: 0.375,-1.4 0.375,-1.575 -0.375,-1.575 -0.375,-1.4 -0.51,-1.4 -0.51,-1.725 0.511,-1.725 0.511,-1.4
  Top Layer region: -0.375,1.4 -0.375,1.575 0.375,1.575 0.375,1.4 0.51,1.4 0.51,1.725 -0.511,1.725 -0.511,1.4
  Top Layer region: 0.51,0.399 0.51,-1.4 0.375,-1.4 0.375,-0.225 0,-0.225 0,0.225 0.375,0.225 0.375,1.4 0.51,1.4
  Top Layer region: -0.511,-0.399 -0.511,1.4 -0.375,1.4 -0.375,0.225 0,0.225 0,-0.225 -0.375,-0.225 -0.375,-1.4 -0.511,-1.4
  silkscreen extent -1.5,-1.07 1.08,0.7, body extent -1.08,-0.7 1.08,0.7, height 0.96
L0402-RF [mm]
  rect 0.4x0.559 smd paste+0 mask+0: 1(-0.454,0) 2(0.454,0)
  body extent -0.55,-0.28 0.55,0.28, height 0.31
LT1529CQ5PBF [mil]
  rect 42.01x90 smd: 1(-134.02,-292.99) 2(-67.01,-292.99) 3(0,-292.99) 4(67.01,-292.99) 5(134.02,-292.99)
  rect 450x450 smd: 6(0,105)
  silkscreen extent -201,-175 201,-157, body extent -199,-314 199,251, height 190
LTST-C170KRKT_V [mm] "SMD, 2-Leads, Body 2x1.25mm"
  rect 1.2x1.2 smd: A(1.05,0) K(-1.05,0)
  silkscreen extent -2.03,-0.64 0.05,0.64, body extent -1,-0.63 1,0.63, height 1.2
M3-HOLE [mm]
  round 6 hole 3.2: 1(0,0)
MAX4003 [mm] "�max"
  oval 1.35x0.4 smd: 1(-2.15,0.975) 2(-2.15,0.325) 3(-2.15,-0.325) 4(-2.15,-0.975) 5(2.15,-0.975) 6(2.15,-0.325) 7(2.15,0.325) 8(2.15,0.975)
  silkscreen extent -2.35,-1.55 1.15,1.9, body extent -1.55,-1.55 1.55,1.55, height 1.1
MOLEX_47346-0001 [mm]
  rect 0.45x1.38 smd: 1(-1.3,2.66) 2(-0.65,2.66) 3(0,2.66) 4(0.65,2.66) 5(1.3,2.66)
  rect 1.475x2.1 smd: SH1(-2.462,2.3) SH2(2.462,2.3)
  rect 2.375x1.9 smd: SH3(-2.913,0) SH6(2.913,0)
  rect 1.175x1.9 smd: SH4(-0.837,0) SH5(0.837,0)
  silkscreen extent -3.75,1.2 3.75,3.75, body extent -4.18,-2.64 4.18,2.79, height 2.7
MS-156HF [mm] "Subminiature Coaxial Switch"
  rect 0.8x2.65 smd paste+0 mask+0.051: G1(1.1,0) G2(-1.1,0)
  rect 0.55x0.55 smd paste-0.3 mask+0.051: IN(0,-1.525)
  rect 0.55x0.7 smd paste-0.3 mask+0.051: OUT(0,1.25)
  body extent -1.36,-1.35 1.34,1.35, height 1.56
NFM18PS [mm] "Feed Through Capacitor"
  rect 0.35x0.35 smd paste+0 mask+0: 1(-0.825,0) 3(0.825,0)
  rect 0.8x0.3 smd paste+0 mask+0: 2(0,0.575) 2(0,-0.575)
  Top Layer region: -0.4,-1.125 0.4,-1.125 0.4,-0.475 -0.4,-0.475
  Top Layer region: -0.4,0.475 0.4,0.475 0.4,1.125 -0.4,1.125
  Top Layer region: -0.3,-0.2 0.3,-0.2 0.3,0.2 -0.3,0.2
  Top Layer region: -0.65,-0.174 -0.6,-0.15 -0.6,0.15 -0.65,0.174 -0.8,0
  Top Layer region: 0.65,0.175 0.6,0.15 0.6,-0.15 0.65,-0.175 0.825,0
  Top Layer region: -0.4,0.425 -0.4,0.3 -0.3,0.2 0.3,0.2 0.4,0.3 0.4,0.425 0,0.625
  Top Layer region: 0.4,-0.425 0.4,-0.3 0.3,-0.2 -0.3,-0.2 -0.4,-0.3 -0.4,-0.425 0,-0.625
  body extent -0.82,-0.43 0.82,0.43, height 0.6
NX3225SA [mm] "20 MHz Crystal Oscillator"
  rect 1.4x1.2 smd paste+0 mask+0: 1(-1.1,-0.8) 2(1.1,-0.8) 3(1.1,0.8) 4(-1.1,0.8)
  silkscreen extent -1.88,-1.45 1.88,1.42, body extent -1.65,-1.3 1.65,1.3, height 1.1
PE62304 [mm] "Digitally Tunable Capacitor for GSM/WCDMA"
  rect 0.45x0.25 smd mask+0.05: 1(-0.975,0.75) 2(-0.975,0.25) 3(-0.975,-0.25) 4(-0.975,-0.75) 6(0.975,-0.75) 7(0.975,-0.25) 8(0.975,0.25) 9(0.975,0.75)
  rect 0.25x0.45 smd mask+0.05: 5(0,-0.975) 10(0,0.975)
  rect 0.95x0.95 smd mask+0.05: 10(0,0)
  silkscreen extent -1.45,-1.04 1.04,1.42, body extent -1,-1.07 1,0.92, height 0.6
PIN_DE_TEST [mm]
  round 1.27 smd paste-10: 1(0,0)
PLUG_THMD_STRIP2 [mm]
  round 2 hole 1 paste+0 mask+0: 1(0,0)
  round 2 / inner round 1.524 / far side round 1.6 hole 1 paste+0 mask+0: 2(2.54,0)
  silkscreen extent -1.27,-1.27 3.81,1.27, body extent -1.27,-1.27 3.81,1.27, height 8.57
QFN50P500X500X100-29N-D [mm]
  rect 1x0.3 smd: 1(-2.35,1.5) 2(-2.35,1) 3(-2.35,0.5) 4(-2.35,0) 5(-2.35,-0.5) 6(-2.35,-1) 7(-2.35,-1.5) 15(2.35,-1.5) 16(2.35,-1) 17(2.35,-0.5) 18(2.35,0) 19(2.35,0.5) 20(2.35,1) 21(2.35,1.5)
  rect 0.3x1 smd: 8(-1.5,-2.35) 9(-1,-2.35) 10(-0.5,-2.35) 11(0,-2.35) 12(0.5,-2.35) 13(1,-2.35) 14(1.5,-2.35) 22(1.5,2.35) 23(1,2.35) 24(0.5,2.35) 25(0,2.35) 26(-0.5,2.35) 27(-1,2.35) 28(-1.5,2.35)
  rect 3.35x3.35 smd: 29(0,0)
  silkscreen extent -2.98,2.13 -2.73,2.37, body extent -2.55,-2.55 2.55,2.55, height 1
QFP50P1200X1200X160-64N [mil]
  rect 58x11 smd: 1(-225,148) 2(-225,128) 3(-225,108) 4(-225,89) 5(-225,69) 6(-225,49) 7(-225,30) 8(-225,10) 9(-225,-10) 10(-225,-30) 11(-225,-49) 12(-225,-69) 13(-225,-89) 14(-225,-108) 15(-225,-128) 16(-225,-148) 33(225,-148) 34(225,-128) 35(225,-108) 36(225,-89) 37(225,-69) 38(225,-49) 39(225,-30) 40(225,-10) 41(225,10) 42(225,30) 43(225,49) 44(225,69) 45(225,89) 46(225,108) 47(225,128) 48(225,148)
  rect 11x58 smd: 17(-148,-225) 18(-128,-225) 19(-108,-225) 20(-89,-225) 21(-69,-225) 22(-49,-225) 23(-30,-225) 24(-10,-225) 25(10,-225) 26(30,-225) 27(49,-225) 28(69,-225) 29(89,-225) 30(108,-225) 31(128,-225) 32(148,-225) 49(148,225) 50(128,225) 51(108,225) 52(89,225) 53(69,225) 54(49,225) 55(30,225) 56(10,225) 57(-10,225) 58(-30,225) 59(-49,225) 60(-69,225) 61(-89,225) 62(-108,225) 63(-128,225) 64(-148,225)
  silkscreen extent -201,-201 201,201, body extent -237,-237 237,237, height 63
RKB2SJK250SMTRLFS [mm]
  rect 1x0.7 smd: 1(-2.25,1.075) 2(2.25,1.075) 3(-2.25,-1.075) 4(2.25,-1.075)
  silkscreen extent -3.3,-1.6 2.1,1.6, body extent -2.68,-1.6 2.68,1.6, height 2.8
SKY13431-374LF [mm] "6 Pin DFN"
  rrect50% 0.35x0.25 smd mask+0.05: 1(-0.725,0.5) 2(-0.725,0) 3(-0.725,-0.5) 4(0.725,-0.5) 5(0.725,0) 6(0.725,0.5)
  rrect30% 0.7x1.2 smd mask+0.05: 7(0,0)
  silkscreen extent -1.35,0.79 -1.25,0.89, body extent -0.75,-0.75 0.75,0.75, height 0.5
SOD3715X135N [mm]
  rrect25% 1.25x0.74 smd: A(1.66,0) K(-1.66,0)
  silkscreen extent -3.01,-0.77 1.35,0.77, body extent -1.85,-0.77 1.85,0.78, height 1.41
ST25RU3993_QFN48_0.5MM_PITCH [mm] "QFN, 48-Leads, Body 7,0x7,0mm (max), Pitch 0,50mm, IPC Medium Density"
  rect 0.55x0.3 smd paste+0 mask+0.05: 1(-3.35,2.75) 12(-3.35,-2.75) 25(3.35,-2.75) 36(3.35,2.75)
  rect 0.75x0.3 smd mask+0.05: 2(-3.25,2.25)
  rect 0.75x0.3 smd paste+0 mask+0.05: 3(-3.25,1.75) 4(-3.25,1.25) 5(-3.25,0.75) 6(-3.25,0.25) 7(-3.25,-0.25) 8(-3.25,-0.75) 9(-3.25,-1.25) 10(-3.25,-1.75) 11(-3.25,-2.25) 26(3.25,-2.25) 27(3.25,-1.75) 28(3.25,-1.25) 29(3.25,-0.75) 30(3.25,-0.25) 31(3.25,0.25) 32(3.25,0.75) 33(3.25,1.25) 34(3.25,1.75) 35(3.25,2.25)
  rect 0.3x0.55 smd paste+0 mask+0.05: 13(-2.75,-3.35) 24(2.75,-3.35) 37(2.75,3.35) 48(-2.75,3.35)
  rect 0.3x0.75 smd paste+0 mask+0.05: 14(-2.25,-3.25) 15(-1.75,-3.25) 16(-1.25,-3.25) 17(-0.75,-3.25) 18(-0.25,-3.25) 19(0.25,-3.25) 20(0.75,-3.25) 21(1.25,-3.25) 22(1.75,-3.25) 23(2.25,-3.25) 38(2.25,3.25) 39(1.75,3.25) 40(1.25,3.25) 41(0.75,3.25) 42(0.25,3.25) 43(-0.25,3.25) 44(-0.75,3.25) 45(-1.25,3.25) 46(-1.75,3.25) 47(-2.25,3.25)
  rect 5.24x5.24 smd mask+0.07: 49(0,0)
  silkscreen extent -3.8,-3.8 3.8,4.15, body extent -3.5,-3.5 3.5,3.5, height 1
TQP9107 [mm] "699 � 960 MHz 2-stage Power Amplifier"
  rect 0.27x0.62 smd mask+0.05: 1(2,1.62) 2(1.5,1.62) 4(0,1.62) 6(-2,1.62) 7(-2,-1.62) 9(0,-1.62) 10(0.5,-1.62) 11(1,-1.62) 12(1.5,-1.62) 13(2,-1.62)
  rect 0.77x0.62 smd mask+0.05: 3(0.75,1.62)
  rect 1.27x0.62 smd mask+0.05: 5(-1,1.62) 8(-1,-1.62)
  rect 4.28x2.16 smd mask+0.05: 14(0,0)
  silkscreen extent -2.53,-2.03 2.53,2.55, body extent -2.25,-1.75 2.25,1.75, height 0.85
TY_TYPE_2.5X2.0MM [mm] "TCXO package Taitien TY type"
  rect 0.8x0.9 smd: 1(-1.025,-0.725) 2(1.025,-0.725) 3(1.025,0.725) 4(-1.025,0.725)
  silkscreen extent -1.7,-2 1.7,1.5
